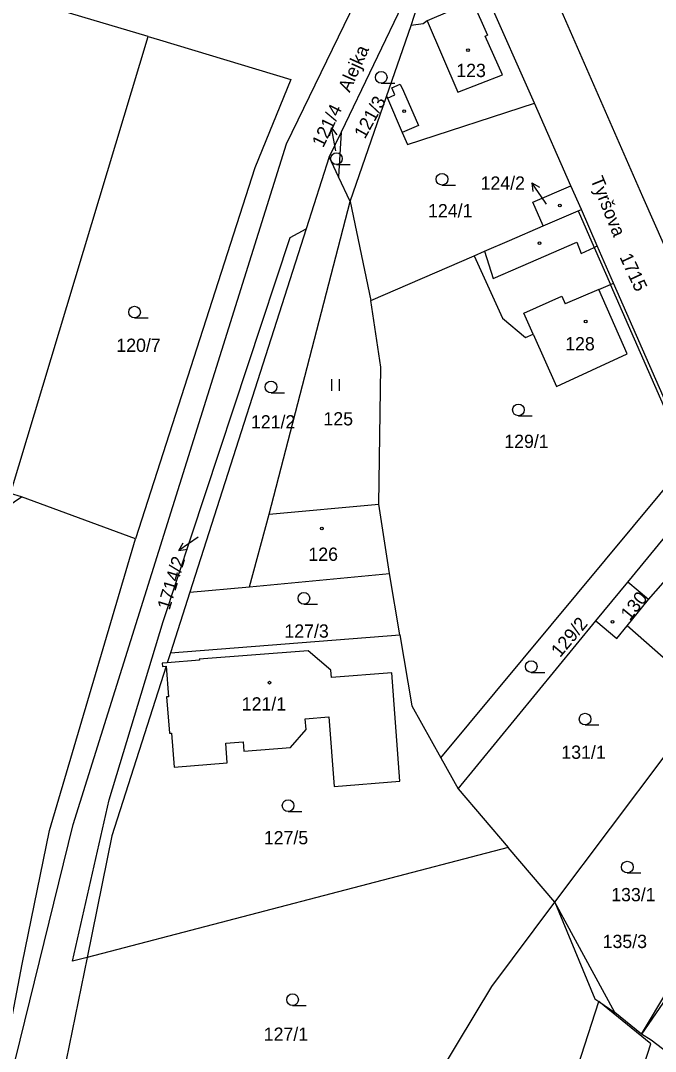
# Model space of a CAD drawing. Extents: x -724107 to -720612, y -1045267 to -1038441.
# Drawn here: x -723028.3 to -722946.8, y -1042451.2 to -1042319 of the extents above; entities that cross this region are included whole.
import ezdxf

# ---------------------------------------------------------------- set-up
doc = ezdxf.new("R2010")
doc.units = 0
for name, color, linetype in [('Hranice parcel', 7, 'Continuous'), ('Parcelní čísla', 7, 'Continuous'), ('Pop  PČ popisy', 7, 'Continuous'), ('Vnitřní kresba', 7, 'Continuous'), ('Značky budov', 7, 'Continuous'), ('Značky kultur', 7, 'Continuous')]:
    doc.layers.add(name, color=color, linetype=linetype)

msp = doc.modelspace()

# ---------------------------------------------------------------- linework, layer by layer
at = {"layer": 'Hranice parcel'}
for p, q in [((-722973.34, -1042304.66), (-722987.16, -1042333.34)), ((-722978.17, -1042319.68), (-722973.34, -1042304.66)), ((-722981.31, -1042328.76), (-722978.17, -1042319.68)), ((-722985.97, -1042342.24), (-722981.31, -1042328.76)), ((-722957.66, -1042340.22), (-722962.35, -1042329.63)), ((-722987.16, -1042333.34), (-722988.68, -1042336.49)), ((-722987.16, -1042333.34), (-722987.46, -1042339.09)), ((-722988.68, -1042336.49), (-722991.64, -1042345.74)), ((-722987.46, -1042339.09), (-722988.68, -1042336.49)), ((-722985.97, -1042342.24), (-722987.46, -1042339.09)), ((-722956.32, -1042343.26), (-722957.66, -1042340.22)), ((-722996.38, -1042382.3), (-722985.97, -1042342.24)), ((-722985.97, -1042342.24), (-722983.33, -1042354.93)), ((-722991.64, -1042345.74), (-723006.57, -1042392.32)), ((-722983.33, -1042354.93), (-722970.08, -1042349.2)), ((-722942.37, -1042375.13), (-722952.19, -1042352.7)), ((-723013.51, -1042385.49), (-723028.14, -1042380.08)), ((-722996.38, -1042382.3), (-722982.32, -1042381.03)), ((-722980.95, -1042389.93), (-722982.32, -1042381.03)), ((-722998.88, -1042391.65), (-722996.38, -1042382.3)), ((-722998.88, -1042391.65), (-722980.95, -1042389.93)), ((-722979.6, -1042397.8), (-722980.95, -1042389.93)), ((-723006.57, -1042392.32), (-722998.88, -1042391.65)), ((-722954.47, -1042396.01), (-722950.37, -1042391.04)), ((-722947.7, -1042393.27), (-722950.37, -1042391.04)), ((-723006.57, -1042392.32), (-723009.05, -1042400.08)), ((-722950.46, -1042396.64), (-722947.7, -1042393.27)), ((-722972.13, -1042417.51), (-722954.47, -1042396.01)), ((-723009.05, -1042400.08), (-722979.6, -1042397.8)), ((-723009.05, -1042400.08), (-723009.46, -1042401.37)), ((-722959.73, -1042432.07), (-722945.45, -1042413.08)), ((-722974.34, -1042413.56), (-722972.13, -1042417.51)), ((-722972.13, -1042417.51), (-722965.72, -1042425.03)), ((-722965.72, -1042425.03), (-723019.74, -1042439.13)), ((-722959.73, -1042432.07), (-722965.72, -1042425.03)), ((-722952.01, -1042446.22), (-722959.73, -1042432.07)), ((-723019.74, -1042439.13), (-723023.77, -1042458.89)), ((-722948.59, -1042449), (-722952.01, -1042446.22))]:
    msp.add_line(p, q, dxfattribs=at)
for points in [[(-723030.78, -1042459.85), (-723021.53, -1042422.08), (-722994.15, -1042334.83), (-722976.41, -1042298.3), (-722916.3, -1042223.03)], [(-723011.9, -1042321.09), (-723028.9, -1042315.98), (-723053.42, -1042308.55)], [(-722962.35, -1042329.63), (-722968.46, -1042315.81), (-722970.3, -1042316.58), (-722976.1, -1042319.07), (-722976.64, -1042319.44), (-722978.17, -1042319.68)], [(-722959.26, -1042316.99), (-722948.46, -1042341.61), (-722934.71, -1042372.64)], [(-723028.14, -1042380.08), (-723029.58, -1042379.65), (-723011.9, -1042321.09)], [(-723011.9, -1042321.09), (-723010.46, -1042321.52), (-722993.6, -1042326.59), (-722998.22, -1042337.92), (-723013.51, -1042385.49)], [(-722981.31, -1042328.76), (-722981.21, -1042328.99), (-722979.31, -1042333.4), (-722978.65, -1042334.91), (-722962.35, -1042329.63)], [(-722961.21, -1042345.37), (-722962.53, -1042342.32), (-722957.66, -1042340.22)], [(-722961.21, -1042345.37), (-722956.73, -1042343.44), (-722956.32, -1042343.26)], [(-722952.19, -1042352.7), (-722954.28, -1042347.92), (-722956.32, -1042343.26)], [(-723019.74, -1042439.13), (-723021.62, -1042439.62), (-723016.89, -1042418.95), (-723009.97, -1042396.06), (-722993.7, -1042346.84), (-722991.64, -1042345.74)], [(-722970.08, -1042349.2), (-722968.73, -1042348.62), (-722965.54, -1042347.24), (-722961.21, -1042345.37)], [(-722970.08, -1042349.2), (-722966.43, -1042357.21), (-722963.48, -1042359.65), (-722962.51, -1042359.23), (-722959.52, -1042365.97), (-722950.45, -1042361.76), (-722954.1, -1042353.52), (-722952.59, -1042352.87), (-722952.19, -1042352.7)], [(-722982.32, -1042381.03), (-722982.05, -1042363.46), (-722983.33, -1042354.93)], [(-722974.34, -1042413.56), (-722942.67, -1042375.48), (-722942.37, -1042375.13)], [(-723031.71, -1042450.6), (-723063.5, -1042404.19), (-723028.14, -1042380.08)], [(-722950.37, -1042391.04), (-722940.89, -1042379.53), (-722940.6, -1042379.18)], [(-723031.71, -1042450.6), (-723029.77, -1042448.96), (-723028.06, -1042440), (-723024.56, -1042422.87), (-723013.51, -1042385.49)], [(-722947.7, -1042393.27), (-722943.29, -1042388.26), (-722936.45, -1042394.03), (-722937.67, -1042395.48), (-722936, -1042396.9), (-722940.79, -1042402.59), (-722942.44, -1042401.14), (-722943.69, -1042402.57), (-722950.46, -1042396.64)], [(-722954.47, -1042396.01), (-722951.79, -1042398.26), (-722950.46, -1042396.64)], [(-722979.6, -1042397.8), (-722978.07, -1042406.9), (-722974.34, -1042413.56)], [(-723009.61, -1042401.81), (-723009.27, -1042405.73), (-723009.54, -1042405.75), (-723009.18, -1042410.4), (-723008.9, -1042410.38), (-723008.55, -1042414.74), (-723001.75, -1042414.21), (-723001.94, -1042411.66), (-722999.72, -1042411.5), (-722999.63, -1042412.71), (-722993.64, -1042412.22), (-722991.65, -1042409.91), (-722991.76, -1042408.57), (-722988.7, -1042408.31), (-722988.03, -1042417.22), (-722979.61, -1042416.56), (-722980.66, -1042402.66), (-722988.39, -1042403.26), (-722988.48, -1042402.32), (-722991.39, -1042399.85), (-723005.34, -1042400.91), (-723005.33, -1042401.04), (-723009.46, -1042401.37)], [(-723009.61, -1042401.81), (-723016.57, -1042423.55), (-723019.74, -1042439.13)], [(-723009.46, -1042401.37), (-723010.11, -1042401.42), (-723010.08, -1042401.85), (-723009.61, -1042401.81)], [(-722948.59, -1042449), (-722938.46, -1042432.07), (-722937.32, -1042430.78)], [(-722936.79, -1042431.31), (-722940.24, -1042436.82), (-722948.59, -1042449)], [(-722983.4, -1042468.75), (-722967.82, -1042442.89), (-722959.73, -1042432.07)], [(-722960.03, -1042469.92), (-722961.98, -1042469.29), (-722961, -1042466.21), (-722962.44, -1042465.74), (-722961.11, -1042461.62), (-722959.68, -1042462.08), (-722956.77, -1042453.11), (-722954.09, -1042444.79), (-722952.01, -1042446.22)], [(-722940.77, -1042453.62), (-722944.3, -1042452.1), (-722947.37, -1042449.77), (-722948.59, -1042449)]]:
    msp.add_lwpolyline(points, dxfattribs=at)
at = {"layer": 'Pop  PČ popisy'}
for p, q in [((-722988.36, -1042332.78), (-722988.68, -1042333.85)), ((-722987.84, -1042335.73), (-722988.36, -1042332.78)), ((-722988.36, -1042332.78), (-722987.69, -1042333.67)), ((-722960.97, -1042342.32), (-722962.69, -1042339.86)), ((-722962.69, -1042339.86), (-722961.71, -1042340.4)), ((-722962.69, -1042339.86), (-722962.53, -1042340.97)), ((-722960.78, -1042342.58), (-722960.97, -1042342.32)), ((-723005.48, -1042385.28), (-723007.97, -1042386.96)), ((-723007.97, -1042386.96), (-723007.42, -1042385.98)), ((-723007.97, -1042386.96), (-723006.86, -1042386.81))]:
    msp.add_line(p, q, dxfattribs=at)
at = {"layer": 'Vnitřní kresba'}
for p, q in [((-722970.3, -1042316.58), (-722968.38, -1042320.91)), ((-722976.1, -1042319.07), (-722972.17, -1042328.22)), ((-722968.66, -1042321.03), (-722968.38, -1042320.91)), ((-722966.43, -1042326), (-722968.66, -1042321.03)), ((-722972.17, -1042328.22), (-722966.43, -1042326)), ((-722980.65, -1042327.65), (-722979.55, -1042327.17)), ((-722979.55, -1042327.17), (-722979.15, -1042328.09)), ((-722981.21, -1042328.99), (-722980.25, -1042328.57)), ((-722980.25, -1042328.57), (-722980.65, -1042327.65)), ((-722979.15, -1042328.09), (-722977.23, -1042332.49)), ((-722977.23, -1042332.49), (-722979.31, -1042333.4)), ((-722956.73, -1042343.44), (-722954.68, -1042348.11)), ((-722964.1, -1042350.56), (-722956.92, -1042347.46)), ((-722956.92, -1042347.46), (-722956.36, -1042348.9)), ((-722956.36, -1042348.9), (-722954.68, -1042348.11)), ((-722954.68, -1042348.11), (-722954.28, -1042347.92)), ((-722954.68, -1042348.11), (-722952.59, -1042352.87)), ((-722968.73, -1042348.62), (-722967.64, -1042352.09)), ((-722967.64, -1042352.09), (-722964.1, -1042350.56)), ((-722954.1, -1042353.52), (-722958.4, -1042355.36)), ((-722942.67, -1042375.48), (-722952.59, -1042352.87)), ((-722963.69, -1042356.56), (-722958.85, -1042354.35)), ((-722958.85, -1042354.35), (-722958.4, -1042355.36)), ((-722962.51, -1042359.23), (-722963.69, -1042356.56)), ((-722959.73, -1042432.07), (-722954.58, -1042444.45)), ((-722954.58, -1042444.45), (-722954.09, -1042444.79)), ((-722947.42, -1042450.2), (-722954.09, -1042444.79)), ((-722949.13, -1042455.58), (-722947.42, -1042450.2))]:
    msp.add_line(p, q, dxfattribs=at)
at = {"layer": 'Značky budov'}
for centre in [(-722970.87, -1042322.84), (-722979.06, -1042330.66), (-722959.07, -1042342.74), (-722961.69, -1042347.56), (-722955.77, -1042357.6), (-722989.62, -1042384.15), (-722952.33, -1042396.13), (-722996.33, -1042403.92)]:
    msp.add_circle(centre, 0.175, dxfattribs=at)
at = {"layer": 'Značky kultur'}
for p, q in [((-722982, -1042327.07), (-722980.25, -1042327.07)), ((-722987.74, -1042337.49), (-722985.99, -1042337.49)), ((-722974.2, -1042340.13), (-722972.45, -1042340.13)), ((-723013.65, -1042357.16), (-723011.9, -1042357.16)), ((-722988.34, -1042366.49), (-722988.34, -1042364.99)), ((-722987.34, -1042366.49), (-722987.34, -1042364.99)), ((-722996.14, -1042366.76), (-722994.39, -1042366.76)), ((-722964.4, -1042369.7), (-722962.65, -1042369.7)), ((-722991.92, -1042393.85), (-722990.17, -1042393.85)), ((-722962.75, -1042402.6), (-722961, -1042402.6)), ((-722955.85, -1042409.34), (-722954.1, -1042409.34)), ((-722993.95, -1042420.43), (-722992.2, -1042420.43)), ((-722950.43, -1042428.31), (-722948.68, -1042428.31)), ((-722993.37, -1042445.31), (-722991.62, -1042445.31))]:
    msp.add_line(p, q, dxfattribs=at)
for centre in [(-722982, -1042326.32), (-722987.74, -1042336.74), (-722974.2, -1042339.38), (-723013.65, -1042356.41), (-722996.14, -1042366.01), (-722964.4, -1042368.95), (-722991.92, -1042393.1), (-722962.75, -1042401.85), (-722955.85, -1042408.59), (-722993.95, -1042419.68), (-722950.43, -1042427.56), (-722993.37, -1042444.56)]:
    msp.add_circle(centre, 0.75, dxfattribs=at)

# ---------------------------------------------------------------- texts
at = {"layer": 'Parcelní čísla'}
for s, p in [('123', (-722972.37, -1042326.28)), ('124/2', (-722969.25, -1042340.72)), ('124/1', (-722975.99, -1042344.26)), ('120/7', (-723015.98, -1042361.51)), ('128', (-722958.4, -1042361.32)), ('121/2', (-722998.71, -1042371.33)), ('125', (-722989.41, -1042370.94)), ('129/1', (-722966.21, -1042373.83)), ('126', (-722991.34, -1042388.3)), ('127/3', (-722994.42, -1042398.15)), ('121/1', (-722999.89, -1042407.49)), ('131/1', (-722958.89, -1042413.68)), ('127/5', (-722997.06, -1042424.64)), ('133/1', (-722952.49, -1042431.94)), ('135/3', (-722953.59, -1042437.94)), ('127/1', (-722997.07, -1042449.83))]:
    msp.add_text(s, height=1.7, dxfattribs=at).set_placement(p)
for s, rotation, p in [('121/4', 64, (-722989.45, -1042335.43)), ('121/3', 61, (-722984.1, -1042334.31)), ('1715', 295, (-722951.46, -1042349.35)), ('1714/2', 73, (-723009.16, -1042394.7)), ('130', 51, (-722950.12, -1042396.06)), ('129/2', 50, (-722959.06, -1042400.78))]:
    msp.add_text(s, height=1.7, rotation=rotation, dxfattribs=at).set_placement(p)
at = {"layer": 'Pop  PČ popisy'}
for s, rotation, p in [('Alejka', 66, (-722986.05, -1042328.34)), ('Tyršova', 292, (-722955.19, -1042339.41))]:
    msp.add_text(s, height=1.7, rotation=rotation, dxfattribs=at).set_placement(p)

doc.saveas('drawing.dxf')
